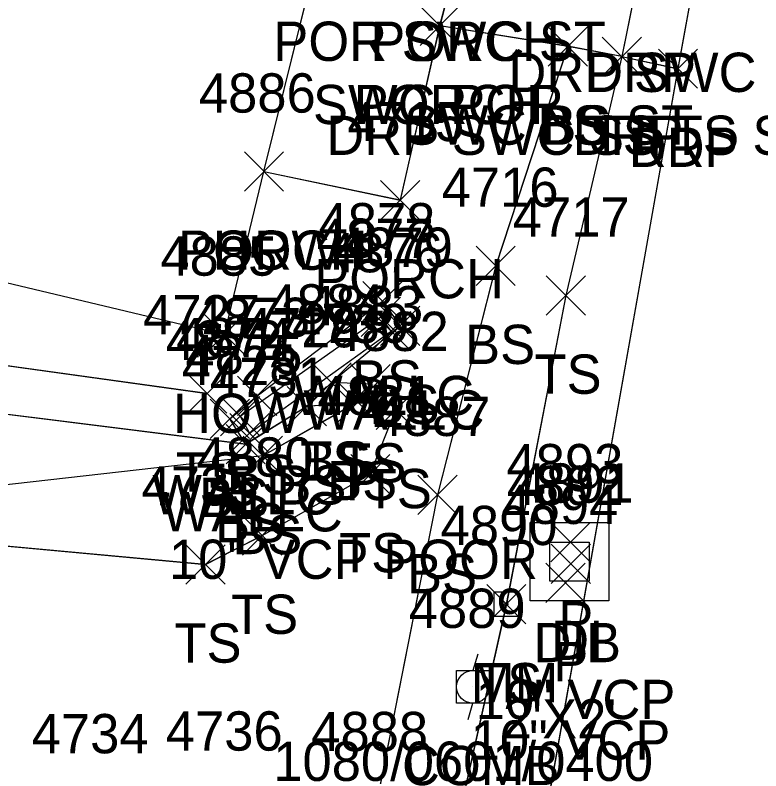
# Model space of a CAD drawing. Extents: x 1554668 to 1563881, y 831386 to 834374.
# Drawn here: x 1562365.8 to 1562403.77, y 833544.34 to 833582.8 of the extents above; entities that cross this region are included whole.
import ezdxf

# ---------------------------------------------------------------- set-up
doc = ezdxf.new("R2010")
doc.units = 0
for name, color, linetype in [('D_A', 7, 'Continuous'), ('D_C', 7, 'Continuous'), ('D_I', 7, 'Continuous'), ('D_TIC', 7, 'Continuous'), ('DS', 7, 'Continuous'), ('L_A', 7, 'Continuous'), ('L_I', 7, 'Continuous'), ('L_TIC', 7, 'Continuous'), ('LBC', 7, 'Continuous'), ('LBF', 7, 'Continuous'), ('LELB', 7, 'Continuous'), ('LW', 7, 'Continuous'), ('P_A', 7, 'Continuous'), ('P_TIC', 7, 'Continuous'), ('PET', 7, 'Continuous'), ('R_A', 7, 'Continuous'), ('R_TIC', 7, 'Continuous'), ('RDP', 7, 'Continuous'), ('RSW', 7, 'Continuous'), ('S_A', 7, 'Continuous'), ('S_C', 7, 'Continuous'), ('S_I', 7, 'Continuous'), ('SRM', 7, 'Continuous'), ('U_A', 7, 'Continuous'), ('U_I', 7, 'Continuous'), ('UP', 7, 'Continuous')]:
    doc.layers.add(name, color=color, linetype=linetype)

msp = doc.modelspace()

# ---------------------------------------------------------------- linework, layer by layer
at = {"layer": 'D_TIC'}
for points in [[(1562382.242, 833562.115), (1562384.242, 833564.115)], [(1562384.242, 833562.115), (1562382.242, 833564.115)], [(1562393.073, 833554.979), (1562395.073, 833556.979)], [(1562395.073, 833554.979), (1562393.073, 833556.979)], [(1562393.086, 833553.874), (1562395.086, 833555.874)], [(1562395.086, 833553.874), (1562393.086, 833555.874)], [(1562392.818, 833552.91), (1562394.818, 833554.91)], [(1562394.818, 833552.91), (1562392.818, 833554.91)]]:
    msp.add_lwpolyline(points, dxfattribs=at)
at = {"layer": 'DS'}
for p, q in [((1562392.026, 833556.992), (1562396.026, 833556.992)), ((1562392.026, 833552.992), (1562392.026, 833556.992)), ((1562396.026, 833556.992), (1562396.026, 833552.992)), ((1562393.026, 833553.992), (1562393.026, 833555.992)), ((1562393.026, 833555.992), (1562395.026, 833555.992)), ((1562395.026, 833555.992), (1562395.026, 833553.992)), ((1562394.031, 833554.993), (1562394.031, 833554.993)), ((1562394.031, 833554.993), (1562394.031, 833554.993)), ((1562395.026, 833553.992), (1562393.026, 833553.992)), ((1562396.026, 833552.992), (1562392.026, 833552.992))]:
    msp.add_line(p, q, dxfattribs=at)
at = {"layer": 'L_TIC'}
for points in [[(1562386.411, 833581.255), (1562388.411, 833583.255)], [(1562388.411, 833581.255), (1562386.411, 833583.255)], [(1562392.943, 833580.209), (1562394.943, 833582.209)], [(1562394.943, 833580.209), (1562392.943, 833582.209)], [(1562395.688, 833579.69), (1562397.688, 833581.69)], [(1562397.688, 833579.69), (1562395.688, 833581.69)], [(1562377.467, 833573.842), (1562379.467, 833575.842)], [(1562379.467, 833573.842), (1562377.467, 833575.842)], [(1562377.467, 833573.842), (1562379.467, 833575.842)], [(1562379.467, 833573.842), (1562377.467, 833575.842)], [(1562384.402, 833572.39), (1562386.402, 833574.39)], [(1562386.402, 833572.39), (1562384.402, 833574.39)], [(1562389.263, 833569.049), (1562391.263, 833571.049)], [(1562391.263, 833569.049), (1562389.263, 833571.049)], [(1562392.829, 833567.534), (1562394.829, 833569.534)], [(1562394.829, 833567.534), (1562392.829, 833569.534)], [(1562383.503, 833567.24), (1562385.503, 833569.24)], [(1562385.503, 833567.24), (1562383.503, 833569.24)], [(1562383.416, 833566.45), (1562385.416, 833568.45)], [(1562385.416, 833566.45), (1562383.416, 833568.45)], [(1562383.416, 833566.45), (1562385.416, 833568.45)], [(1562385.416, 833566.45), (1562383.416, 833568.45)], [(1562384.398, 833565.994), (1562386.398, 833567.994)], [(1562386.398, 833565.994), (1562384.398, 833567.994)], [(1562383.941, 833565.715), (1562385.941, 833567.715)], [(1562385.941, 833565.715), (1562383.941, 833567.715)], [(1562375.453, 833565.544), (1562377.453, 833567.544)], [(1562377.453, 833565.544), (1562375.453, 833567.544)], [(1562380.906, 833563.108), (1562382.906, 833565.108)], [(1562382.906, 833563.108), (1562380.906, 833565.108)], [(1562380.906, 833563.108), (1562382.906, 833565.108)], [(1562382.906, 833563.108), (1562380.906, 833565.108)], [(1562382.887, 833563.017), (1562384.887, 833565.017)], [(1562384.887, 833563.017), (1562382.887, 833565.017)], [(1562374.571, 833562.556), (1562376.571, 833564.556)], [(1562376.571, 833562.556), (1562374.571, 833564.556)], [(1562377.124, 833562.426), (1562379.124, 833564.426)], [(1562379.124, 833562.426), (1562377.124, 833564.426)], [(1562379.655, 833561.898), (1562381.655, 833563.898)], [(1562381.655, 833561.898), (1562379.655, 833563.898)], [(1562382.242, 833562.115), (1562384.242, 833564.115)], [(1562384.242, 833562.115), (1562382.242, 833564.115)], [(1562376.248, 833561.395), (1562378.248, 833563.395)], [(1562378.248, 833561.395), (1562376.248, 833563.395)], [(1562376.248, 833561.395), (1562378.248, 833563.395)], [(1562378.248, 833561.395), (1562376.248, 833563.395)], [(1562384.186, 833561.711), (1562386.186, 833563.711)], [(1562386.186, 833561.711), (1562384.186, 833563.711)], [(1562375.723, 833561.262), (1562377.723, 833563.262)], [(1562377.723, 833561.262), (1562375.723, 833563.262)], [(1562376.729, 833560.531), (1562378.729, 833562.531)], [(1562378.729, 833560.531), (1562376.729, 833562.531)], [(1562376.536, 833559.973), (1562378.536, 833561.973)], [(1562378.536, 833559.973), (1562376.536, 833561.973)], [(1562376.536, 833559.973), (1562378.536, 833561.973)], [(1562378.536, 833559.973), (1562376.536, 833561.973)], [(1562377.409, 833559.372), (1562379.409, 833561.372)], [(1562379.409, 833559.372), (1562377.409, 833561.372)], [(1562382.881, 833558.447), (1562384.881, 833560.447)], [(1562384.881, 833558.447), (1562382.881, 833560.447)], [(1562386.308, 833557.387), (1562388.308, 833559.387)], [(1562388.308, 833557.387), (1562386.308, 833559.387)], [(1562377.381, 833555.316), (1562379.381, 833557.316)], [(1562379.381, 833555.316), (1562377.381, 833557.316)], [(1562374.497, 833553.85), (1562376.497, 833555.85)], [(1562376.497, 833553.85), (1562374.497, 833555.85)], [(1562389.806, 833551.834), (1562391.806, 833553.834)], [(1562391.806, 833551.834), (1562389.806, 833553.834)]]:
    msp.add_lwpolyline(points, dxfattribs=at)
at = {"layer": 'LBC'}
for points in [[(1562357.514, 833611.155), (1562352.144, 833589.704), (1562340.526, 833592.051), (1562336.604, 833576.033), (1562376.453, 833566.55), (1562378.467, 833574.848)], [(1562357.514, 833611.155), (1562352.144, 833589.704), (1562340.526, 833592.051), (1562336.604, 833576.033), (1562376.453, 833566.55), (1562378.467, 833574.848)], [(1562357.514, 833611.155), (1562352.144, 833589.704), (1562340.526, 833592.051), (1562336.604, 833576.033), (1562376.453, 833566.55), (1562378.467, 833574.848)], [(1562357.516, 833611.149), (1562352.143, 833589.694), (1562340.527, 833592.042), (1562336.607, 833576.026), (1562376.453, 833566.544), (1562378.467, 833574.842)]]:
    msp.add_lwpolyline(points, dxfattribs=at)
at = {"layer": 'LBF'}
for points in [[(1562378.467, 833574.848), (1562383.657, 833595.806)], [(1562378.467, 833574.848), (1562383.657, 833595.806)], [(1562378.467, 833574.848), (1562383.657, 833595.806)], [(1562378.467, 833574.842), (1562383.659, 833595.802)], [(1562383.657, 833595.806), (1562390.415, 833594.07), (1562390.31, 833593.491), (1562388.254, 833585.477), (1562387.413, 833582.263), (1562385.405, 833573.398)], [(1562383.657, 833595.806), (1562390.415, 833594.07), (1562390.31, 833593.491), (1562388.254, 833585.477), (1562387.413, 833582.263), (1562385.405, 833573.398)], [(1562383.657, 833595.806), (1562390.415, 833594.07), (1562390.31, 833593.491), (1562388.254, 833585.477), (1562387.413, 833582.263), (1562385.405, 833573.398)], [(1562383.659, 833595.802), (1562390.416, 833594.065), (1562390.309, 833593.484), (1562388.256, 833585.473), (1562387.411, 833582.255), (1562385.402, 833573.39)], [(1562378.467, 833574.848), (1562385.405, 833573.398)], [(1562378.467, 833574.848), (1562385.405, 833573.398)], [(1562378.467, 833574.848), (1562385.405, 833573.398)], [(1562378.467, 833574.842), (1562385.402, 833573.39)]]:
    msp.add_lwpolyline(points, dxfattribs=at)
at = {"layer": 'LELB'}
for points in [[(1562393.943, 833581.209), (1562390.263, 833570.049), (1562387.308, 833558.387), (1562384.134, 833542.349), (1562385.189, 833527.753)], [(1562393.945, 833581.217), (1562390.265, 833570.058), (1562387.308, 833558.392), (1562384.135, 833542.357), (1562385.19, 833527.76)], [(1562393.945, 833581.217), (1562390.265, 833570.058), (1562387.308, 833558.392), (1562384.135, 833542.357), (1562385.19, 833527.76)], [(1562393.945, 833581.217), (1562390.265, 833570.058), (1562387.308, 833558.392), (1562384.135, 833542.357), (1562385.19, 833527.76)], [(1562396.688, 833580.69), (1562393.829, 833568.534), (1562390.806, 833552.834), (1562385.189, 833527.753), (1562375.528, 833523.195)], [(1562396.691, 833580.699), (1562393.83, 833568.541), (1562390.805, 833552.836), (1562385.19, 833527.76), (1562375.529, 833523.202)], [(1562396.691, 833580.699), (1562393.83, 833568.541), (1562390.805, 833552.836), (1562385.19, 833527.76), (1562375.529, 833523.202)], [(1562396.691, 833580.699), (1562393.83, 833568.541), (1562390.805, 833552.836), (1562385.19, 833527.76), (1562375.529, 833523.202)], [(1562314.72, 833576.723), (1562333.685, 833569.966), (1562356.425, 833566.212), (1562375.567, 833563.564)], [(1562314.72, 833576.723), (1562333.685, 833569.966), (1562356.425, 833566.212), (1562375.567, 833563.564)], [(1562314.72, 833576.723), (1562333.685, 833569.966), (1562356.425, 833566.212), (1562375.567, 833563.564)], [(1562314.721, 833576.719), (1562333.689, 833569.959), (1562356.428, 833566.204), (1562375.571, 833563.556)], [(1562333.689, 833569.959), (1562355.503, 833563.727), (1562377.536, 833560.973), (1562380.655, 833562.898), (1562383.242, 833563.115), (1562378.409, 833560.372), (1562350.211, 833557.187), (1562347.164, 833543.802), (1562343.65, 833536.193), (1562311.237, 833538.561), (1562279.364, 833544.679), (1562255.457, 833556.378), (1562235.314, 833564.422)], [(1562333.685, 833569.966), (1562355.503, 833563.735), (1562377.534, 833560.98), (1562380.653, 833562.905), (1562383.235, 833563.123), (1562378.407, 833560.38), (1562350.205, 833557.196), (1562347.164, 833543.808), (1562343.65, 833536.199), (1562311.235, 833538.569), (1562279.358, 833544.684), (1562255.46, 833556.387), (1562235.315, 833564.43)], [(1562333.685, 833569.966), (1562355.503, 833563.735), (1562377.534, 833560.98), (1562380.653, 833562.905), (1562383.235, 833563.123), (1562378.407, 833560.38), (1562350.205, 833557.196), (1562347.164, 833543.808), (1562343.65, 833536.199), (1562311.235, 833538.569), (1562279.358, 833544.684), (1562255.46, 833556.387), (1562235.315, 833564.43)], [(1562333.685, 833569.966), (1562355.503, 833563.735), (1562377.534, 833560.98), (1562380.653, 833562.905), (1562383.235, 833563.123), (1562378.407, 833560.38), (1562350.205, 833557.196), (1562347.164, 833543.808), (1562343.65, 833536.199), (1562311.235, 833538.569), (1562279.358, 833544.684), (1562255.46, 833556.387), (1562235.315, 833564.43)], [(1562377.534, 833560.98), (1562376.723, 833562.268), (1562378.125, 833563.431), (1562384.503, 833568.241), (1562385.398, 833566.997), (1562381.906, 833564.111)], [(1562377.534, 833560.98), (1562376.723, 833562.268), (1562378.125, 833563.431), (1562384.503, 833568.241), (1562385.398, 833566.997), (1562381.906, 833564.111)], [(1562377.534, 833560.98), (1562376.723, 833562.268), (1562378.125, 833563.431), (1562384.503, 833568.241), (1562385.398, 833566.997), (1562381.906, 833564.111)], [(1562377.536, 833560.973), (1562376.723, 833562.262), (1562378.124, 833563.426), (1562384.503, 833568.24), (1562385.398, 833566.994), (1562381.906, 833564.108)], [(1562350.205, 833557.196), (1562375.493, 833554.859), (1562378.38, 833556.318), (1562383.88, 833559.45), (1562385.187, 833562.72), (1562383.887, 833564.017), (1562381.906, 833564.111)], [(1562350.205, 833557.196), (1562375.493, 833554.859), (1562378.38, 833556.318), (1562383.88, 833559.45), (1562385.187, 833562.72), (1562383.887, 833564.017), (1562381.906, 833564.111)], [(1562350.205, 833557.196), (1562375.493, 833554.859), (1562378.38, 833556.318), (1562383.88, 833559.45), (1562385.187, 833562.72), (1562383.887, 833564.017), (1562381.906, 833564.111)], [(1562350.211, 833557.187), (1562375.497, 833554.85), (1562378.381, 833556.316), (1562383.881, 833559.447), (1562385.186, 833562.711), (1562383.887, 833564.017), (1562381.906, 833564.108)]]:
    msp.add_lwpolyline(points, dxfattribs=at)
at = {"layer": 'LW'}
for points in [[(1562377.248, 833562.395), (1562384.416, 833567.45)], [(1562377.248, 833562.395), (1562377.729, 833561.531), (1562384.941, 833566.715), (1562384.416, 833567.45)], [(1562377.249, 833562.402), (1562384.416, 833567.455)], [(1562377.249, 833562.402), (1562377.729, 833561.538), (1562384.941, 833566.719), (1562384.416, 833567.455)], [(1562377.249, 833562.402), (1562384.416, 833567.455)], [(1562377.249, 833562.402), (1562377.729, 833561.538), (1562384.941, 833566.719), (1562384.416, 833567.455)], [(1562377.249, 833562.402), (1562384.416, 833567.455)], [(1562377.249, 833562.402), (1562377.729, 833561.538), (1562384.941, 833566.719), (1562384.416, 833567.455)]]:
    msp.add_lwpolyline(points, dxfattribs=at)
at = {"layer": 'P_TIC'}
for points in [[(1562398.545, 833579.078), (1562400.545, 833581.078)], [(1562400.545, 833579.078), (1562398.545, 833581.078)]]:
    msp.add_lwpolyline(points, dxfattribs=at)
at = {"layer": 'PET'}
for points in [[(1562446.514, 833813.563), (1562435.7, 833762.854), (1562429.669, 833734.264), (1562422.437, 833699.227), (1562413.341, 833652.592), (1562406.134, 833614.879), (1562402.03, 833593.791), (1562399.545, 833580.082), (1562389.601, 833524.029), (1562386.342, 833504.136), (1562384.709, 833497.669), (1562380.24, 833469.601), (1562374.637, 833437.636), (1562367.889, 833393.469), (1562360.289, 833352.08)], [(1562446.514, 833813.563), (1562435.7, 833762.854), (1562429.669, 833734.264), (1562422.437, 833699.227), (1562413.341, 833652.592), (1562406.134, 833614.879), (1562402.03, 833593.791), (1562399.545, 833580.082), (1562389.601, 833524.029), (1562386.342, 833504.136), (1562384.709, 833497.669), (1562380.24, 833469.601), (1562374.637, 833437.636), (1562367.889, 833393.469), (1562360.289, 833352.08)], [(1562446.514, 833813.563), (1562435.7, 833762.854), (1562429.669, 833734.264), (1562422.437, 833699.227), (1562413.341, 833652.592), (1562406.134, 833614.879), (1562402.03, 833593.791), (1562399.545, 833580.082), (1562389.601, 833524.029), (1562386.342, 833504.136), (1562384.709, 833497.669), (1562380.24, 833469.601), (1562374.637, 833437.636), (1562367.889, 833393.469), (1562360.289, 833352.08)], [(1562446.513, 833813.556), (1562435.697, 833762.843), (1562429.671, 833734.255), (1562422.435, 833699.223), (1562413.341, 833652.586), (1562406.134, 833614.874), (1562402.03, 833593.785), (1562399.545, 833580.078), (1562389.599, 833524.021), (1562386.34, 833504.127), (1562384.71, 833497.666), (1562380.238, 833469.596), (1562374.637, 833437.628), (1562367.889, 833393.463), (1562360.289, 833352.078)]]:
    msp.add_lwpolyline(points, dxfattribs=at)
at = {"layer": 'R_TIC'}
for points in [[(1562386.411, 833581.255), (1562388.411, 833583.255)], [(1562388.411, 833581.255), (1562386.411, 833583.255)], [(1562392.943, 833580.209), (1562394.943, 833582.209)], [(1562394.943, 833580.209), (1562392.943, 833582.209)], [(1562395.688, 833579.69), (1562397.688, 833581.69)], [(1562397.688, 833579.69), (1562395.688, 833581.69)], [(1562395.688, 833579.69), (1562397.688, 833581.69)], [(1562397.688, 833579.69), (1562395.688, 833581.69)], [(1562398.545, 833579.078), (1562400.545, 833581.078)], [(1562400.545, 833579.078), (1562398.545, 833581.078)]]:
    msp.add_lwpolyline(points, dxfattribs=at)
at = {"layer": 'RDP'}
for points in [[(1562422.435, 833699.223), (1562417.216, 833699.796), (1562415.617, 833695.787), (1562417.09, 833691.936), (1562414.806, 833677.714), (1562412.869, 833666.812), (1562407.067, 833641.681), (1562399.623, 833594.371), (1562397.329, 833583.892), (1562396.688, 833580.69), (1562399.545, 833580.078)], [(1562422.437, 833699.227), (1562417.215, 833699.806), (1562415.617, 833695.794), (1562417.089, 833691.946), (1562414.804, 833677.723), (1562412.87, 833666.818), (1562407.069, 833641.687), (1562399.62, 833594.374), (1562397.33, 833583.898), (1562396.691, 833580.699), (1562399.545, 833580.082)], [(1562422.437, 833699.227), (1562417.215, 833699.806), (1562415.617, 833695.794), (1562417.089, 833691.946), (1562414.804, 833677.723), (1562412.87, 833666.818), (1562407.069, 833641.687), (1562399.62, 833594.374), (1562397.33, 833583.898), (1562396.691, 833580.699), (1562399.545, 833580.082)], [(1562422.437, 833699.227), (1562417.215, 833699.806), (1562415.617, 833695.794), (1562417.089, 833691.946), (1562414.804, 833677.723), (1562412.87, 833666.818), (1562407.069, 833641.687), (1562399.62, 833594.374), (1562397.33, 833583.898), (1562396.691, 833580.699), (1562399.545, 833580.082)]]:
    msp.add_lwpolyline(points, dxfattribs=at)
at = {"layer": 'RSW'}
for points in [[(1562396.688, 833580.69), (1562393.943, 833581.209), (1562387.411, 833582.255)], [(1562396.691, 833580.699), (1562393.945, 833581.217), (1562387.413, 833582.263)], [(1562396.691, 833580.699), (1562393.945, 833581.217), (1562387.413, 833582.263)], [(1562396.691, 833580.699), (1562393.945, 833581.217), (1562387.413, 833582.263)]]:
    msp.add_lwpolyline(points, dxfattribs=at)
at = {"layer": 'SRM'}
msp.add_lwpolyline([(1562390.181, 833553.459), (1562391.431, 833553.459), (1562391.431, 833552.209), (1562390.181, 833552.209)], close=True, dxfattribs=at)
msp.add_circle((1562390.806, 833552.834), 0.0833, dxfattribs=at)
at = {"layer": 'UP'}
for p, q in [((1562389.357, 833550.286), (1562389.107, 833549.452)), ((1562388.274, 833547.786), (1562388.274, 833549.452)), ((1562388.274, 833549.452), (1562389.94, 833549.452)), ((1562389.94, 833549.452), (1562389.94, 833547.786)), ((1562389.107, 833548.619), (1562389.107, 833548.619)), ((1562389.94, 833547.786), (1562388.274, 833547.786)), ((1562388.857, 833546.952), (1562389.107, 833547.786))]:
    msp.add_line(p, q, dxfattribs=at)
msp.add_circle((1562389.107, 833548.619), 0.833, dxfattribs=at)

# ---------------------------------------------------------------- texts
at = {"layer": 'D_A'}
for s, p in [('P', (1562382.62, 833558.115)), ('P', (1562393.451, 833550.979)), ('DIB', (1562392.188, 833549.874)), ('DI', (1562393.087, 833549.993)), ('P', (1562393.196, 833548.91))]:
    msp.add_text(s, height=2, dxfattribs=at).set_placement(p)
at = {"layer": 'D_C'}
for s, p in [('10" VCP POOR', (1562373.628, 833554.115)), ('10" VCP', (1562389.246, 833546.979)), ("2'X2'", (1562390.63, 833545.993)), ('10" VCP', (1562388.991, 833544.91))]:
    msp.add_text(s, height=2, dxfattribs=at).set_placement(p)
at = {"layer": 'D_I'}
for s, p in [('4730', (1562379.895, 833566.115)), ('4893', (1562390.813, 833558.979)), ('4892', (1562390.826, 833557.874)), ('4891', (1562391.338, 833557.993)), ('4894', (1562390.558, 833556.91))]:
    msp.add_text(s, height=2, dxfattribs=at).set_placement(p)
at = {"layer": 'L_A'}
for s, p in [('PORCH', (1562383.878, 833580.473)), ('PORCH', (1562383.033, 833577.255)), ('BS', (1562392.384, 833576.209)), ('TS', (1562395.097, 833575.69)), ('PORCH', (1562374.089, 833569.842)), ('HOW', (1562375.853, 833569.842)), ('PORCH', (1562381.024, 833568.39)), ('BS', (1562388.704, 833565.049)), ('TS', (1562392.238, 833563.534)), ('BS', (1562382.944, 833563.24)), ('WALLC', (1562379.952, 833562.45)), ('WALLC', (1562379.952, 833562.45)), ('BS', (1562383.839, 833561.994)), ('HOW', (1562373.839, 833561.544)), ('WALLC', (1562380.476, 833561.715)), ('TS', (1562380.316, 833559.108)), ('BS', (1562380.347, 833559.108)), ('TS', (1562382.297, 833559.017)), ('TS', (1562373.98, 833558.556)), ('BS', (1562376.565, 833558.426)), ('BS', (1562379.096, 833557.898)), ('BS', (1562381.683, 833558.115)), ('TS', (1562383.595, 833557.711)), ('WALLC', (1562372.784, 833557.395)), ('WALLC', (1562372.784, 833557.395)), ('BS', (1562375.164, 833557.262)), ('WALLC', (1562373.264, 833556.531)), ('BS', (1562375.977, 833555.973)), ('BS', (1562375.977, 833555.973)), ('BS', (1562376.85, 833555.372)), ('TS', (1562382.29, 833554.447)), ('BS', (1562385.749, 833553.387)), ('TS', (1562376.79, 833551.316)), ('TS', (1562373.906, 833549.85)), ('TS', (1562389.216, 833547.834))]:
    msp.add_text(s, height=2, dxfattribs=at).set_placement(p)
at = {"layer": 'L_I'}
for s, p in [('4886', (1562375.152, 833577.842)), ('4886', (1562375.152, 833577.842)), ('4715', (1562382.709, 833576.39)), ('4716', (1562387.515, 833573.049)), ('4717', (1562391.136, 833571.534)), ('4878', (1562381.244, 833571.24)), ('4877', (1562381.156, 833570.45)), ('4877', (1562381.156, 833570.45)), ('4879', (1562382.13, 833569.994)), ('4885', (1562373.193, 833569.544)), ('4876', (1562381.626, 833569.715)), ('4884', (1562378.646, 833567.108)), ('4884', (1562378.646, 833567.108)), ('4883', (1562380.627, 833567.017)), ('4727', (1562372.311, 833566.556)), ('4873', (1562374.865, 833566.426)), ('4730', (1562379.895, 833566.115)), ('4729', (1562377.387, 833565.898)), ('4882', (1562381.926, 833565.711)), ('4872', (1562373.463, 833565.262)), ('4874', (1562373.989, 833565.395)), ('4874', (1562373.989, 833565.395)), ('4875', (1562374.469, 833564.531)), ('4728', (1562374.276, 833563.973)), ('4728', (1562374.276, 833563.973)), ('4731', (1562375.716, 833563.372)), ('4881', (1562381.188, 833562.447)), ('4887', (1562384.048, 833561.387)), ('4880', (1562375.034, 833559.316)), ('4735', (1562372.237, 833557.85)), ('4890', (1562387.46, 833555.834)), ('4734', (1562366.641, 833545.24)), ('4736', (1562373.469, 833545.375)), ('4888', (1562380.874, 833545.349))]:
    msp.add_text(s, height=2, dxfattribs=at).set_placement(p)
at = {"layer": 'P_A'}
msp.add_text('RDP', height=2, dxfattribs=at).set_placement((1562397.033, 833575.078))
at = {"layer": 'R_A'}
for s, p in [('POR SWC ST', (1562378.941, 833580.473)), ('DRP SWC', (1562390.912, 833578.892)), ('DRP', (1562394.818, 833578.892)), ('SWC POR', (1562380.962, 833577.255)), ('SWC BS ST', (1562385.605, 833576.209)), ('DRP SWC ST TS ST', (1562381.64, 833575.69)), ('DRP', (1562394.176, 833575.69)), ('DRP', (1562397.033, 833575.078))]:
    msp.add_text(s, height=2, dxfattribs=at).set_placement(p)
at = {"layer": 'S_A'}
msp.add_text('MM', height=2, dxfattribs=at).set_placement((1562388.995, 833547.834))
at = {"layer": 'S_C'}
msp.add_text('1080/0601/0400', height=2, dxfattribs=at).set_placement((1562378.94, 833543.834))
at = {"layer": 'S_I'}
msp.add_text('4890', height=2, dxfattribs=at).set_placement((1562387.46, 833555.834))
at = {"layer": 'U_A'}
msp.add_text('COMB', height=2, dxfattribs=at).set_placement((1562385.493, 833543.619))
at = {"layer": 'U_I'}
msp.add_text('4889', height=2, dxfattribs=at).set_placement((1562385.839, 833551.619))

doc.saveas('drawing.dxf')
